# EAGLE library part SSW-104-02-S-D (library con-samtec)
THROUGH-HOLE .025" SQ POST SOCKET Source: Samtec SSW.pdf
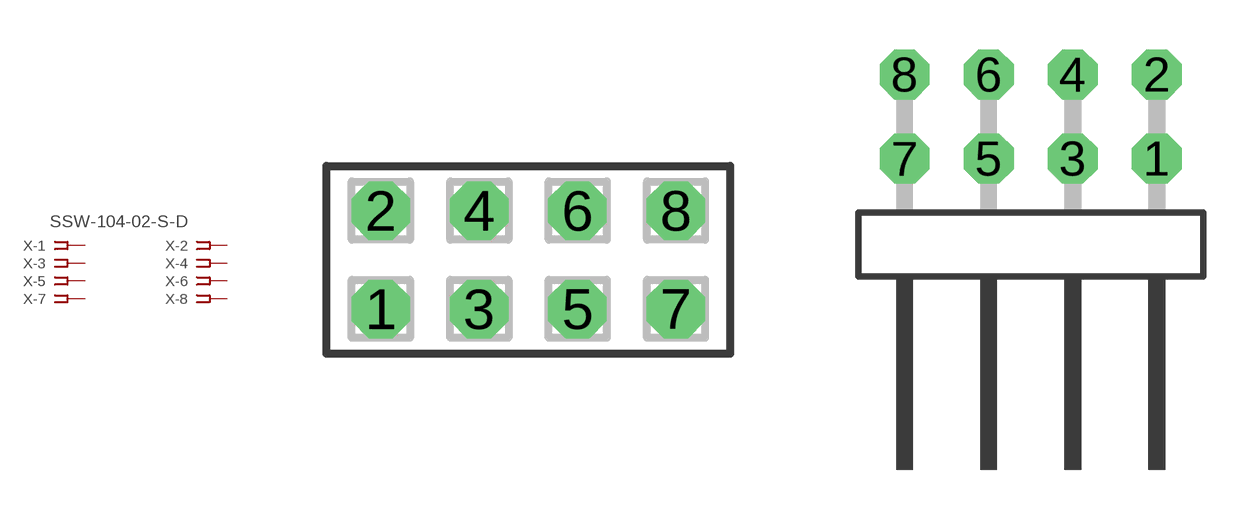
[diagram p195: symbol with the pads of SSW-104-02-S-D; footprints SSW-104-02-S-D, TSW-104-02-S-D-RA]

Designator prefix X; gates -1=FPINV -2=FPIN -3=FPIN -4=FPIN -5=FPIN -6=FPIN -7=FPIN -8=FPIN

## SSW-104-02-S-D (MPN: SSW-104-02-S-D; OC_FARNELL: 1668346; OC_NEWARK: 11P9382)  [SSW-104-02-S-D]
1  -1:1  pas
2  -2:1  pas
3  -3:1  pas
4  -4:1  pas
5  -5:1  pas
6  -6:1  pas
7  -7:1  pas
8  -8:1  pas

## SSW-104-02-S-D-RA (MPN: SSW-104-02-S-D-RA; OC_FARNELL: unknown; OC_NEWARK: 11P9383)  [TSW-104-02-S-D-RA]
Pads as for SSW-104-02-S-D

## Footprint SSW-104-02-S-D (pad centres in mm)
THROUGH-HOLE .025" SQ POST SOCKET Source: Samtec SSW.pdf
drill 1 pad 1.5 octagon: 1 -3.81,-1.27; 2 -3.81,1.27; 3 -1.27,-1.27; 4 -1.27,1.27; 5 1.27,-1.27; 6 1.27,1.27; 7 3.81,-1.27; 8 3.81,1.27

## Footprint TSW-104-02-S-D-RA (pad centres in mm)
THROUGH-HOLE .025" SQ POST HEADER Source: Samtec TSW.pdf
drill 1 pad 1.5 octagon: 1 3.81,1.524; 2 3.81,4.064; 3 1.27,1.524; 4 1.27,4.064; 5 -1.27,1.524; 6 -1.27,4.064; 7 -3.81,1.524; 8 -3.81,4.064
